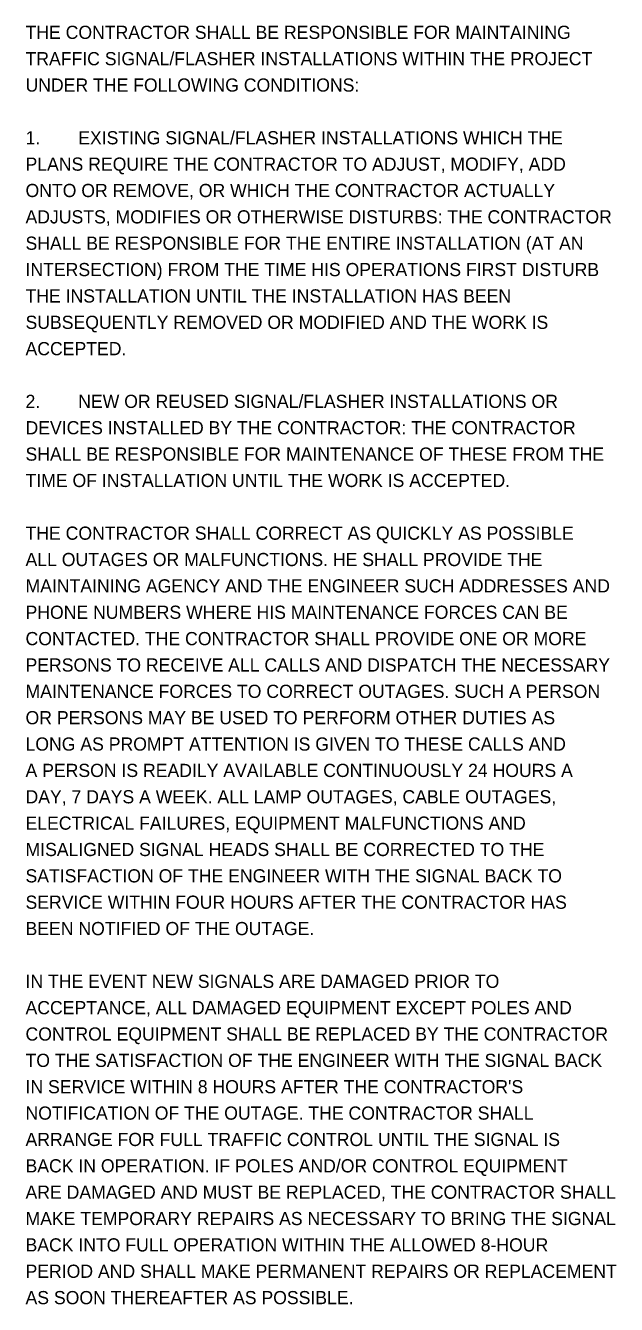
# Model space of a CAD drawing. Extents: x -11.8 to 65.2, y -26.4 to 34.6.
# Drawn here: x 58.95 to 65.22, y 1.72 to 15.3 of the extents above; entities that cross this region are included whole.
import ezdxf

# ---------------------------------------------------------------- set-up
doc = ezdxf.new("R2010")
doc.units = 0
doc.layers.add('SH_Text', color=7, linetype='Continuous')

msp = doc.modelspace()

# ---------------------------------------------------------------- texts
at = {"layer": 'SH_Text'}
for s, p in [('THE CONTRACTOR SHALL BE RESPONSIBLE FOR MAINTAINING ', (58.945, 15.163)), ('TRAFFIC SIGNAL/FLASHER INSTALLATIONS WITHIN THE PROJECT ', (58.945, 14.883)), ('UNDER THE FOLLOWING CONDITIONS:', (58.945, 14.603)), ('1.', (58.945, 14.043)), ('EXISTING SIGNAL/FLASHER INSTALLATIONS WHICH THE ', (59.505, 14.043)), ('PLANS REQUIRE THE CONTRACTOR TO ADJUST, MODIFY, ADD ', (58.945, 13.763)), ('ONTO OR REMOVE, OR WHICH THE CONTRACTOR ACTUALLY ', (58.945, 13.483)), ('ADJUSTS, MODIFIES OR OTHERWISE DISTURBS: THE CONTRACTOR ', (58.945, 13.203)), ('SHALL BE RESPONSIBLE FOR THE ENTIRE INSTALLATION (AT AN ', (58.945, 12.923)), ('INTERSECTION) FROM THE TIME HIS OPERATIONS FIRST DISTURB ', (58.945, 12.643)), ('THE INSTALLATION UNTIL THE INSTALLATION HAS BEEN ', (58.945, 12.363)), ('SUBSEQUENTLY REMOVED OR MODIFIED AND THE WORK IS ', (58.945, 12.083)), ('ACCEPTED.', (58.945, 11.803)), ('2.', (58.945, 11.243)), ('NEW OR REUSED SIGNAL/FLASHER INSTALLATIONS OR ', (59.505, 11.243)), ('DEVICES INSTALLED BY THE CONTRACTOR: THE CONTRACTOR ', (58.945, 10.963)), ('SHALL BE RESPONSIBLE FOR MAINTENANCE OF THESE FROM THE ', (58.945, 10.683)), ('TIME OF INSTALLATION UNTIL THE WORK IS ACCEPTED. ', (58.945, 10.403)), ('THE CONTRACTOR SHALL CORRECT AS QUICKLY AS POSSIBLE ', (58.945, 9.843)), ('ALL OUTAGES OR MALFUNCTIONS. HE SHALL PROVIDE THE ', (58.945, 9.563)), ('MAINTAINING AGENCY AND THE ENGINEER SUCH ADDRESSES AND ', (58.945, 9.283)), ('PHONE NUMBERS WHERE HIS MAINTENANCE FORCES CAN BE ', (58.945, 9.003)), ('CONTACTED. THE CONTRACTOR SHALL PROVIDE ONE OR MORE ', (58.945, 8.723)), ('PERSONS TO RECEIVE ALL CALLS AND DISPATCH THE NECESSARY ', (58.945, 8.443)), ('MAINTENANCE FORCES TO CORRECT OUTAGES. SUCH A PERSON ', (58.945, 8.163)), ('OR PERSONS MAY BE USED TO PERFORM OTHER DUTIES AS ', (58.945, 7.883)), ('LONG AS PROMPT ATTENTION IS GIVEN TO THESE CALLS AND ', (58.945, 7.603)), ('A PERSON IS READILY AVAILABLE CONTINUOUSLY 24 HOURS A ', (58.945, 7.323)), ('DAY, 7 DAYS A WEEK. ALL LAMP OUTAGES, CABLE OUTAGES, ', (58.945, 7.043)), ('ELECTRICAL FAILURES, EQUIPMENT MALFUNCTIONS AND ', (58.945, 6.763)), ('MISALIGNED SIGNAL HEADS SHALL BE CORRECTED TO THE ', (58.945, 6.483)), ('SATISFACTION OF THE ENGINEER WITH THE SIGNAL BACK TO ', (58.945, 6.203)), ('SERVICE WITHIN FOUR HOURS AFTER THE CONTRACTOR HAS ', (58.945, 5.923)), ('BEEN NOTIFIED OF THE OUTAGE.', (58.945, 5.643)), ('IN THE EVENT NEW SIGNALS ARE DAMAGED PRIOR TO ', (58.945, 5.083)), ('ACCEPTANCE, ALL DAMAGED EQUIPMENT EXCEPT POLES AND ', (58.945, 4.803)), ('CONTROL EQUIPMENT SHALL BE REPLACED BY THE CONTRACTOR ', (58.945, 4.523)), ('TO THE SATISFACTION OF THE ENGINEER WITH THE SIGNAL BACK ', (58.945, 4.243)), ("IN SERVICE WITHIN 8 HOURS AFTER THE CONTRACTOR'S ", (58.945, 3.963)), ('NOTIFICATION OF THE OUTAGE. THE CONTRACTOR SHALL ', (58.945, 3.683)), ('ARRANGE FOR FULL TRAFFIC CONTROL UNTIL THE SIGNAL IS ', (58.945, 3.403)), ('BACK IN OPERATION. IF POLES AND/OR CONTROL EQUIPMENT ', (58.945, 3.123)), ('ARE DAMAGED AND MUST BE REPLACED, THE CONTRACTOR SHALL ', (58.945, 2.843)), ('MAKE TEMPORARY REPAIRS AS NECESSARY TO BRING THE SIGNAL ', (58.945, 2.563)), ('BACK INTO FULL OPERATION WITHIN THE ALLOWED 8-HOUR ', (58.945, 2.283)), ('PERIOD AND SHALL MAKE PERMANENT REPAIRS OR REPLACEMENT ', (58.945, 2.003)), ('AS SOON THEREAFTER AS POSSIBLE.', (58.945, 1.723))]:
    msp.add_text(s, height=0.14, dxfattribs=at).set_placement(p)

doc.saveas('drawing.dxf')
